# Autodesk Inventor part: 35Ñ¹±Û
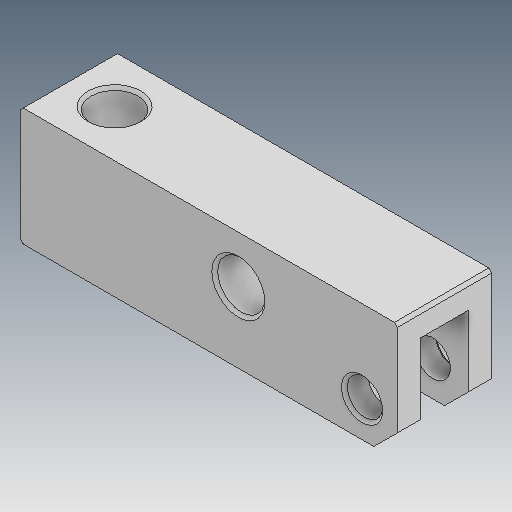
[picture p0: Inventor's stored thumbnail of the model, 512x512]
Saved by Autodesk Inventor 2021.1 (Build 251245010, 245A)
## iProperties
Created: 2019-04
Part Number: 35Ñ¹±Û
Material: Ogólny
Document SubType Name: Modeling
Designer: user
Density: 1 g/cm^3
Appearance: Domyślna
Author: user
Revision Number: ÈÎºÎ
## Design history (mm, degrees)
feature "ÊäÈë1"
node "Bryła1"
